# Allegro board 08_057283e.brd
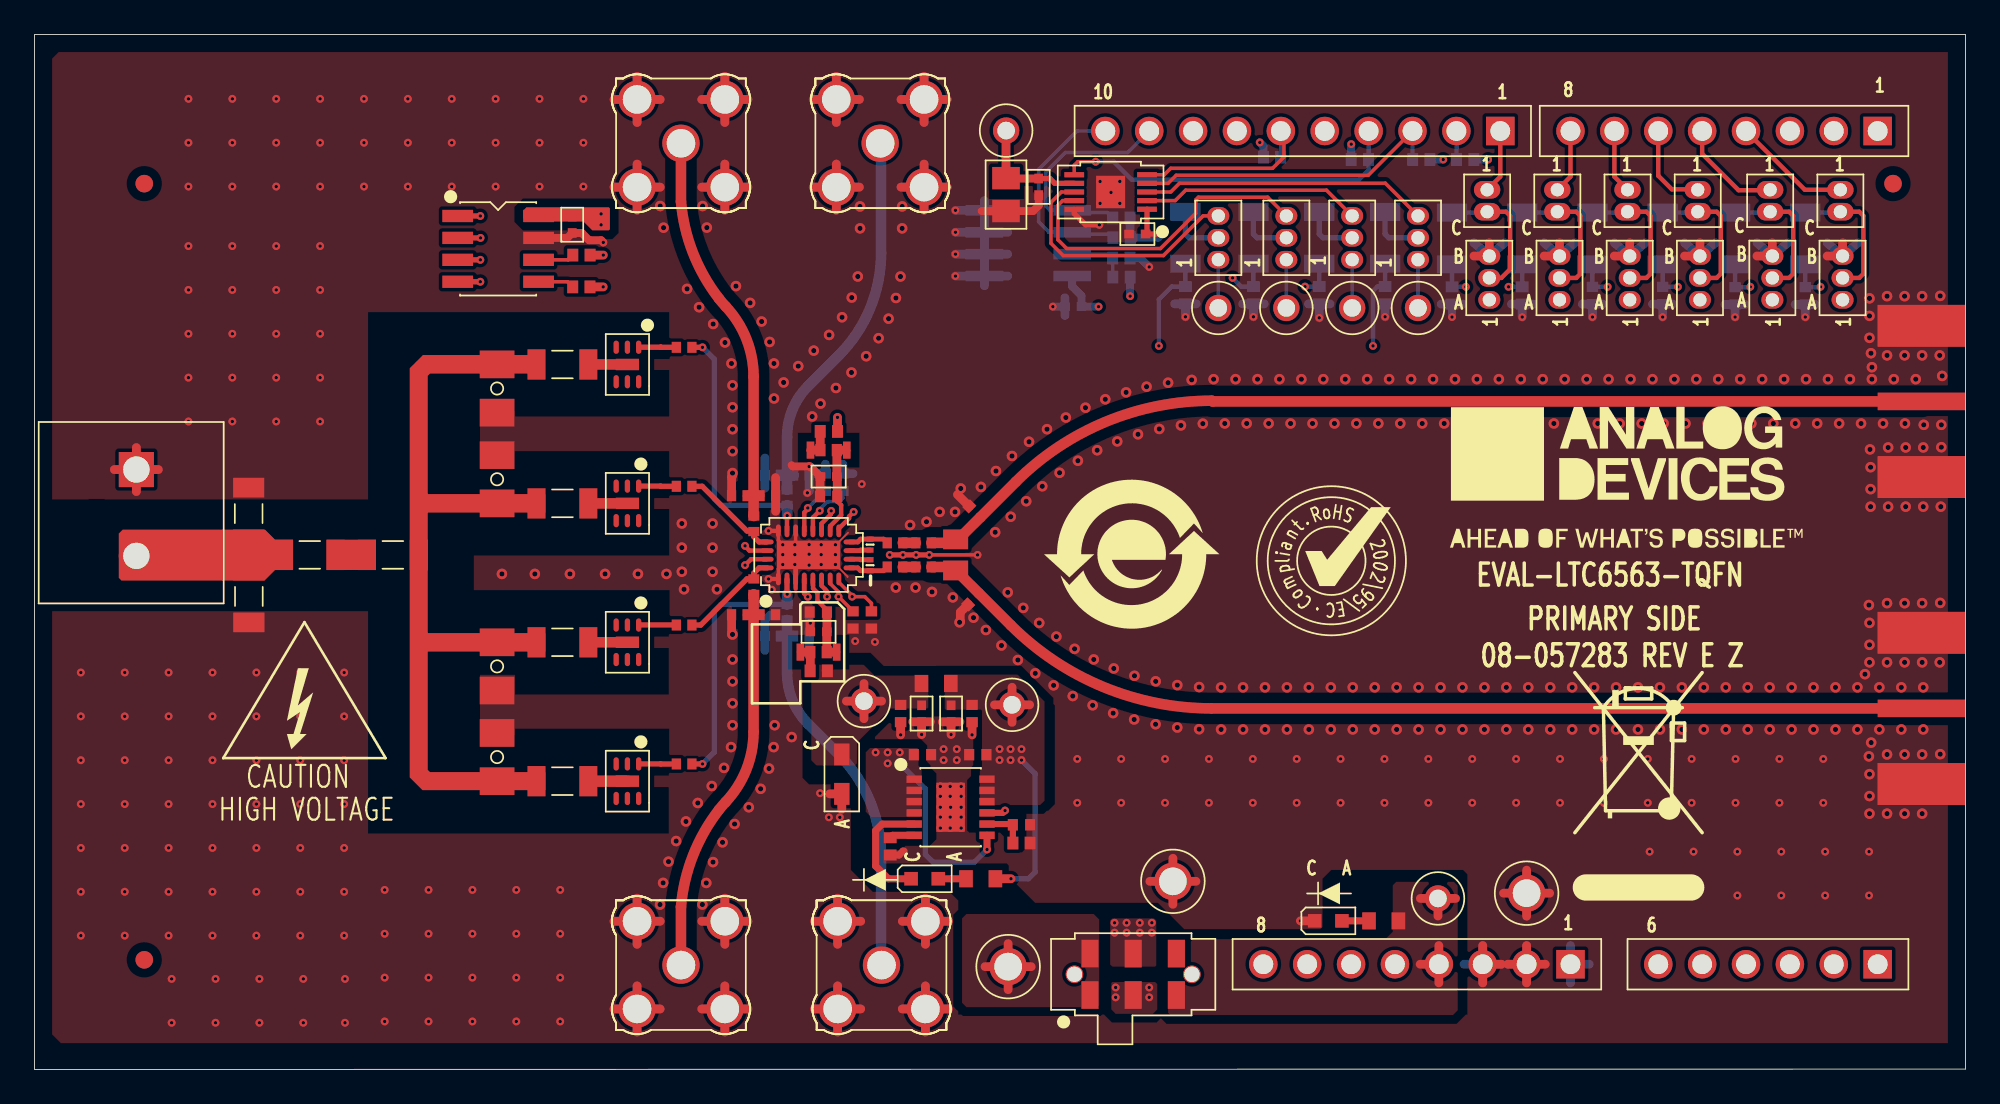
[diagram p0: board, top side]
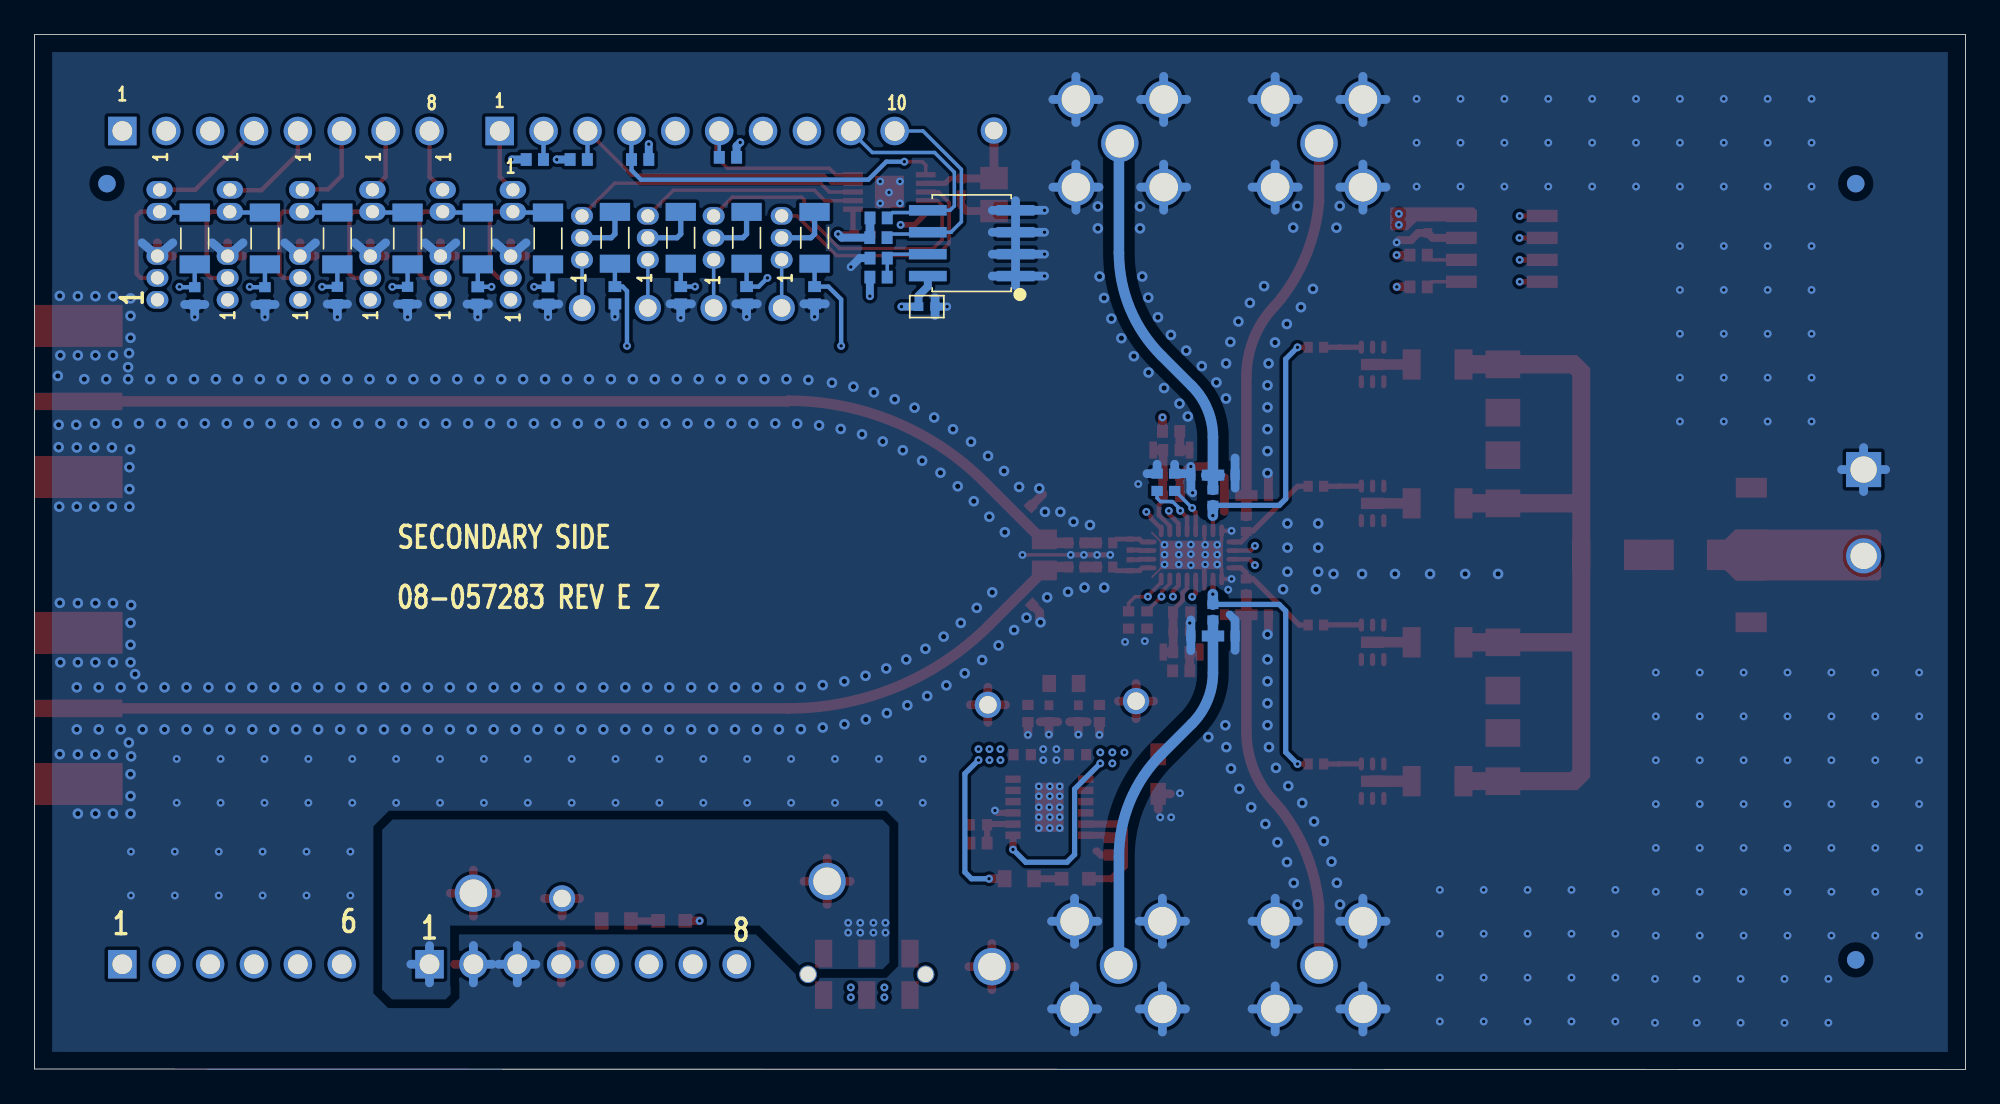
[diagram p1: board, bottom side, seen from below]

Outline 111.76 x 59.94 mm; copper layers: TOP, L2_GND, L3_VCC, L4_SIGNAL, L5_GND, BOTTOM. Coordinates in mm from the lower left corner of the outline.
Outline path: 0,59.94 0,0 111.76,0.03 111.76,59.94 0,59.94

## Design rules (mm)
constraint set DEFAULT: min track width 0.203

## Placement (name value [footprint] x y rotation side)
ADJ0  FTS-103-01-F-S  [CN1X3H159]  104.65 44.58 90 top
ADJ1  FTS-103-01-F-S  [CN1X3H159]  100.58 44.58 90 top
C1  680pF  [C0402]  45.77 34.01 270 bottom
C2  680pF  [C0402]  47.37 26.03 90 top
C3  680pF  [C0402]  46.79 34.01 270 bottom
C4  680pF  [C0402]  48.44 26.03 270 top
C5  0.1uF  [C0402H22]  60.12 44.18 180 bottom
C6  0.1uF  [C0402H22]  31.12 48.93 90 top
C7  1000pF  [C1206]  12.39 32.2 270 top
C8  1000pF  [C1206]  12.4 27.4 90 top
C9  0.1uF  [C1206H71]  26.77 39.44 90 top
C10  0.1uF  [C1206H71]  26.77 34.19 270 top
C11  0.1uF  [C1206H71]  26.77 23.35 90 top
C12  0.1uF  [C1206H71]  26.77 18.09 270 top
C13  10uF  [C0805H53]  56.23 50.67 90 top
C14  4.7uF  [C0402]  51.39 18.23 180 top
C15  0.47uF  [C0402H22]  57.12 14.17 180 top
C16  10uF  [C0402]  54.59 18.23 0 top
C17  0.1uF  [C0402H22]  45.38 25.35 0 top
C18  680pF  [C0402]  45.36 26.49 0 top
C19  1uF  [C0402H22]  51.34 20.62 90 top
C20  680pF  [C0402]  45.96 33.19 0 top
C21  10uF  [C0402]  50.13 20.62 90 top
C22  0.1uF  [C0402H22]  45.96 34.34 0 top
C25  10uF  [C0402]  54.26 20.62 90 top
C26  0.1uF  [C0402H22]  63.83 48.39 0 top
C27  0.1uF  [C0402H22]  58.12 51.12 90 top
C28  4.7pF  [C0805]  53.31 29.8 90 top
C29  1uF  [C0402H22]  53.05 20.62 90 top
CHSEL0  FTS-103-01-F-S  [CN1X3H159]  84.2 44.58 90 top
CHSEL1  FTS-103-01-F-S  [CN1X3H159]  88.27 44.58 90 top
CM  BLK  [CNKEY5001TP]  68.52 44.11 90 top
D1  501557  [DFN6_2X2_PAD1_35X0_65]  34.32 40.83 180 top
D2  501557  [DFN6_2X2_PAD1_35X0_65]  34.32 32.79 180 top
D3  501557  [DFN6_2X2_PAD1_35X0_65]  34.32 24.74 180 top
D4  501557  [DFN6_2X2_PAD1_35X0_65]  34.32 16.7 180 top
D5  SD101CWS-7-F  [SOD323]  46.72 17.11 270 top
DS1  SML-LX0603GW-TR  [LED0603-2]  74.88 8.61 0 top
DS2  SML-LX0603GW-TR  [LED0603-2]  51.52 11.05 0 top
E1  1.8K OHM AT 100MEGHZ  [L0402]  45.38 24.17 0 top
E2  1.8K OHM AT 100MEGHZ  [L0402]  45.96 35.87 180 top
GND  BLK  [CNLOOPTP]  65.89 10.9 0 top
GND1  BLK  [CNLOOPTP]  86.36 10.21 0 top
HI  BLK  [CNKEY5001TP]  80.07 44.11 90 top
IN1  SMA-J-P-H-ST-TH1  [CNSMASQ276H381]  48.95 53.64 90 top
IN2  SMA-J-P-H-ST-TH1  [CNSMASQ276H381]  37.41 53.64 90 top
IN3  SMA-J-P-H-ST-TH1  [CNSMASQ276H381]  37.41 6.05 270 top
IN4  SMA-J-P-H-ST-TH1  [CNSMASQ276H381]  49.02 6.05 270 top
MUX  FTS-103-01-F-S  [CN1X3H159]  92.33 44.58 90 top
NOREF  -  []  15.37 20.83 0 top
NOREF#2  -  []  -231.78 -199.64 0 top
NOREF#3  -  []  139.57 144.91 0 top
NOREF#4  -  []  0 59.94 0 top
NOREF#5  -  []  6.35 6.35 0 top
NOREF#6  -  []  113.03 0 0 top
NOREF#7  -  []  102.11 26.67 0 top
NOREF#8  -  []  -231.78 -199.64 0 top
NOREF#9  -  []  63.5 29.84 0 top
NOREF#10  -  []  -47.62 251.21 0 top
NOREF#11  -  []  158.11 260.48 0 top
NOREF#12  -  []  0 59.94 0 top
NOREF#13  -  []  -231.78 -199.64 0 top
NOREF#14  -  []  91.57 34.29 0 top
NOREF#15  -  []  0 59.94 270 top
NOREF#16  -  []  111.76 0 90 top
NOREF#17  -  []  0 0 0 top
NOREF#18  -  [unnamed#2]  6.35 6.35 0 top
NOREF#19  -  []  208.91 -40.39 0 top
NOREF#20  -  [unnamed#2]  6.35 51.31 0 top
NOREF#21  -  []  111.76 59.94 180 top
NOREF#22  -  []  0 0 0 top
NOREF#23  -  []  6.35 6.35 0 top
NOREF#24  -  []  75.06 29.46 0 top
NOREF#25  -  []  112.39 79.12 270 top
NOREF#26  -  [unnamed#2]  107.57 51.31 0 top
NOREF#27  -  []  43.18 3.56 270 top
NOREF#28  -  []  0 0 0 top
NOREF#29  -  []  57.66 74.42 0 top
NOREF#30  -  []  -1.27 32.26 0 top
NOREF#31  -  []  111.76 0 0 top
NOREF#32  -  [unnamed#2]  107.57 51.31 180 bottom
NOREF#33  -  [unnamed#2]  6.35 51.31 180 bottom
NOREF#34  -  [unnamed#2]  6.35 6.35 180 bottom
OFFSET  BLK  [CNKEY5001TP]  76.26 44.11 90 top
OUT  142-0701-801  [CNJOHNSON142-0701-801]  109.22 38.69 0 top
OUTBAR  142-0701-801  [CNJOHNSON142-0701-801]  109.22 20.91 0 top
P1  FTS-103-01-F-S  [CN1X3H159]  68.52 46.9 90 top
P2  FTS-103-01-F-S  [CN1X3H159]  72.45 46.9 90 top
P3  FTS-103-01-F-S  [CN1X3H159]  76.26 46.9 90 top
P4  FTS-103-01-F-S  [CN1X3H159]  80.07 46.9 90 top
P7  MC000046  [CNMULTICOMP-MC000046]  5.89 34.75 270 top
P8  SSQ-110-03-G-S  [CNSAMTECSSQ-110-XX-X-S]  84.84 54.36 180 top
P9  SSQ-108-03-G-S  [CNSAMTECSSQ-108-XX-X-S]  106.68 54.36 180 top
P10  SSQ-106-03-G-S  [CNSAMTECSSQ-106-XX-X-S]  106.68 6.1 180 top
P11  SSQ-108-03-G-S  [CNSAMTECSSQ-108-XX-X-S]  88.9 6.1 180 top
P13  FTS-102-01-F-S  [CNSAMTECFTS-102-01-F-S]  88.14 50.95 270 top
P14  FTS-102-01-F-S  [CNSAMTECFTS-102-01-F-S]  96.27 50.95 270 top
P15  FTS-102-01-F-S  [CNSAMTECFTS-102-01-F-S]  92.2 50.95 270 top
P19  FTS-102-01-F-S  [CNSAMTECFTS-102-01-F-S]  84.07 50.95 270 top
P20  FTS-102-01-F-S  [CNSAMTECFTS-102-01-F-S]  104.52 50.95 270 top
P21  FTS-102-01-F-S  [CNSAMTECFTS-102-01-F-S]  100.46 50.95 270 top
R1  100  [R0402]  42.72 34.43 0 bottom
R2  100  [R0402]  40.79 33.23 0 top
R3  100  [R0402]  42.44 26.34 180 top
R4  100  [R0402]  44.38 25.11 180 bottom
R5  100  [R0402]  44.38 34.43 180 bottom
R6  100  [R0402]  42.44 33.23 180 top
R7  100  [R0402]  40.79 26.34 0 top
R8  100  [R0402]  42.72 25.11 0 bottom
R9  33  [R1206]  70.55 48.17 270 bottom
R10  33  [R1206]  66.61 48.17 270 bottom
R11  33  [R1206]  74.36 48.17 270 bottom
R12  33  [R1206]  78.17 48.17 270 bottom
R13  10K  [R0402]  70.55 44.84 90 bottom
R14  10K  [R0402]  66.61 44.84 90 bottom
R15  10K  [R0402]  74.36 44.84 90 bottom
R16  10K  [R0402]  78.17 44.84 90 bottom
R17  33  [R1206]  94.23 48.13 270 bottom
R18  33  [R1206]  90.17 48.13 270 bottom
R19  33  [R1206]  102.49 48.13 270 bottom
R20  33  [R1206]  98.42 48.13 270 bottom
R21  0.1uF  [C0402H22]  94.23 44.83 90 bottom
R22  0.1uF  [C0402H22]  90.17 44.83 90 bottom
R23  0.1uF  [C0402H22]  102.49 44.81 90 bottom
R24  0.1uF  [C0402H22]  98.42 44.81 90 bottom
R25  33  [R1206]  86.11 48.13 270 bottom
R26  33  [R1206]  82.04 48.13 270 bottom
R27  10K  [R0402]  86.11 44.83 270 bottom
R28  10K  [R0402]  82.04 44.83 270 bottom
R29  10K  [R1206]  15.93 29.8 0 top
R30  10K  [R1206]  20.74 29.8 0 top
R31  49.9  [R1206]  30.55 40.83 0 top
R32  49.9  [R1206]  30.55 32.79 0 top
R33  49.9  [R1206]  30.55 24.74 0 top
R34  49.9  [R1206]  30.55 16.7 0 top
R39  0  [R0402]  37.6 41.83 0 top
R40  0  [R0402]  37.6 33.78 0 top
R41  0  [R0402]  37.6 25.74 0 top
R42  0  [R0402]  37.6 17.7 0 top
R43  10K  [R0402]  31.65 47.17 0 top
R44  10K  [R0402]  31.65 45.33 0 top
R45  33.2K  [R0402]  57.12 13.11 180 top
R46  0  [R0402]  45.39 23.09 180 top
R47  0  [R0201]  48.36 30.4 270 top
R48  0  [R0201]  48.36 29.21 270 top
R49  0  [R0603]  52.18 22.36 0 top
R50  0  [R0402]  45.97 36.96 0 top
R51  0  [R0402]  49.8 30.5 0 top
R52  0  [R0402]  49.8 29.11 0 top
R53  0  [R0402]  51.46 30.5 0 top
R54  0  [R0402]  51.46 29.11 0 top
R55  49.9  [R0402]  54.42 32.3 135 top
R56  49.9  [R0402]  54.35 27.25 45 top
R57  10K  [R0402]  62.92 48.18 0 bottom
R58  10K  [R0402]  62.91 45.89 0 bottom
R59  0  [R0402]  62.9 46.99 180 bottom
R60  10K  [R0402]  62.91 49.32 0 bottom
R61  150  [R0603]  78.09 8.61 0 top
R62  0  [R0402]  49.53 12.92 90 top
R63  110  [R0603]  54.76 11.05 0 top
R64  2K  [R0402]  43.55 33.12 270 bottom
R65  2K  [R0402]  41.63 31.61 270 top
R66  2K  [R0402]  41.63 27.97 90 top
R67  2K  [R0402]  43.55 26.48 90 bottom
R68  10K  [R0402]  82.8 52.7 0 bottom
R69  10K  [R0402]  80.26 52.7 0 bottom
R70  10K  [R0402]  76.71 52.7 180 bottom
R71  10K  [R0402]  71.63 52.83 180 bottom
REF  BLK  [CNKEY5001TP]  56.24 54.38 0 top
S1  JS202011JAQN  [SWSML354W142H142]  63.59 5.51 0 top
SHDN  FTS-103-01-F-S  [CN1X3H159]  96.39 44.58 90 top
TILT  BLK  [CNKEY5001TP]  72.45 44.11 90 top
TP4  BLK  [CNKEY5001TP]  81.23 9.91 0 top
U1  ADT7311WTRZ  [SO8-2]  26.83 47.53 270 top
U2  LTC2634IMSE-LMI10#PBF  [MSOP10_PAD1_88X1_68]  62.28 50.82 90 top
U3  LT3045HMSE#PBF  [MSOP12_PAD2_845X1_651]  53.02 15.19 270 top
U4  LTC6563  [QFN24_5X3_PAD3_65X1_65]  44.8 29.8 0 top
U5  24AA256-I/SN  [SO8]  57.52 47.86 90 bottom
VCCI  BLK  [CNKEY5001TP]  48.01 21.34 0 top
VCCO  BLK  [CNKEY5001TP]  56.58 21.12 0 top
VIN  RED  [CNLOOPTP]  56.35 5.96 0 top

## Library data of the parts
ADJ0 ADJ1 CHSEL0 CHSEL1 MUX P1-P4 SHDN = CN3P: Tolerance: N/A; User Part Number: UPN; alternate symbols: (); part number: CN3P_TH-FTS-103-01-F-S,E021702,CN1X3H159; tolerance: N/A
C1-C4 C18 C20 = CAP: User Part Number: UPN; Tolerance: 10; alternate symbols: (C0402L); part number: CAP_SM-680PF,50V,10,E033952,C0402; tolerance: 10
C5 C6 C17 C22 C26 C27 = CAP: Tolerance: 10; User Part Number: UPN; alternate symbols: (); part number: CAP_SM-0.1UF,50V,10,E018452,C0402H22; tolerance: 10
C7 C8 = CAP: User Part Number: UPN; Tolerance: 20; alternate symbols: (C1206L); part number: CAP_SM-1000PF,2000V,20,E033416,C1206; tolerance: 20
C9-C12 = CAP: Tolerance: 10; User Part Number: UPN; alternate symbols: (); part number: CAP_SM-0.1UF,450V,10,E019762,C1206H71; tolerance: 10
C13 = CAP: Tolerance: 10; User Part Number: UPN; alternate symbols: (); part number: CAP_SM-10UF,16V,10,E006166,C0805H53; tolerance: 10
C14 = CAP: User Part Number: UPN; Tolerance: 10; alternate symbols: (C0402L); part number: CAP_SM-4.7UF,10V,10,E028571,C0402; tolerance: 10
C15 = CAP: User Part Number: UPN; Tolerance: 10; alternate symbols: C0402; part number: CAP_SM-0.47UF,10V,10,E030959,C0402H22; tolerance: 10
C16 C21 C25 = CAP: User Part Number: UPN; Tolerance: 20; alternate symbols: (C0402L); part number: CAP_SM-10UF,10V,20,E020928,C0402; tolerance: 20
C19 C29 = CAP: Tolerance: 20; User Part Number: UPN; alternate symbols: (); part number: CAP_SM-1UF,25V,20,E028570,C0402H22; tolerance: 20
C28 = CAP: User Part Number: UPN; Tolerance: 0.1pF; alternate symbols: (); part number: CAP_SM-4.7PF,250V,0.1PF,E024708,C0805; tolerance: 0.1pF
CM HI OFFSET REF TILT TP4 VCCI VCCO = CNTP1P: Tolerance: N/A; User Part Number: UPN; alternate symbols: (); part number: CNTP1P_TH-BLK,E005347,CNKEY5001TP; tolerance: N/A
D1-D4 = DIOPHOTO6P_V3: Tolerance: N/A; User Part Number: UPN; alternate symbols: (); part number: DIOPHOTO6P_V3_SM-501557,200V,N/A,E034727,DFN6_2X2_PAD1_35X0_65; tolerance: N/A
D5 = DIOSCHOTTKY: Tolerance: N/A; User Part Number: UPN; alternate symbols: (); part number: DIOSCHOTTKY_SM-SD101CWS-7-F,40V,N/A,E032391,SOD323; tolerance: N/A
DS1 DS2 = DIOLED: Tolerance: N/A; User Part Number: UPN; alternate symbols: (); part number: DIOLED_SM-SML-LX0603GW-TR,N/A,N/A,E018702,LED0603-2; tolerance: N/A
E1 E2 = FERRITE: User Part Number: UPN; Tolerance: 25; alternate symbols: (L0402L); part number: FERRITE_SM-1.8K OHM AT 100MEGHZ,25,E025769,L0402; tolerance: 25
GND GND1 = CNTP1P: User Part Number: UPN; Tolerance: N/A; alternate symbols: (); part number: CNTP1P_TH-BLK,E000948,CNLOOPTP; tolerance: N/A
IN1-IN4 = CNBNC5P: User Part Number: UPN; Tolerance: N/A; alternate symbols: (); part number: CNBNC5P_TH-SMA-J-P-H-ST-TH1,E035738,CNSMASQ276H381; tolerance: N/A
OUT OUTBAR = CNBNC5P: User Part Number: UPN; Tolerance: N/A; alternate symbols: (); part number: CNBNC5P_SM-142-0701-801,E000914,CNJOHNSON142-0701-801; tolerance: N/A
P7 = CN2P: User Part Number: UPN; Tolerance: N/A; alternate symbols: (); part number: CN2P_TH-MC000046,E024272,CNMULTICOMP-MC000046; tolerance: N/A
P8 = CN10P: User Part Number: UPN; Tolerance: N/A; alternate symbols: (); part number: CN10P_TH-SSQ-110-03-G-S,E020479,CNSAMTECSSQ-110-XX-X-S; tolerance: N/A
P9 P11 = CN8P_A: User Part Number: UPN; Tolerance: N/A; alternate symbols: (); part number: CN8P_A_TH-SSQ-108-03-G-S,E020478,CNSAMTECSSQ-108-XX-X-S; tolerance: N/A
P10 = CN6P: User Part Number: UPN; Tolerance: N/A; alternate symbols: (); part number: CN6P_TH-SSQ-106-03-G-S,E020477,CNSAMTECSSQ-106-XX-X-S; tolerance: N/A
P13-P15 P19-P21 = CN2P: Tolerance: N/A; User Part Number: UPN; alternate symbols: (); part number: CN2P_TH-FTS-102-01-F-S,E021754,CNSAMTECFTS-102-01-F-S; tolerance: N/A
R1-R8 = RES: User Part Number: UPN; Tolerance: 1; alternate symbols: (R0402L); part number: RES_SM-100,E016329,1/10W,1,R0402; tolerance: 1
R9-R12 R17-R20 R25 R26 = RES: User Part Number: UPN; Tolerance: 2; alternate symbols: (R1206L); part number: RES_SM-33,E004120,1/4W,2,R1206; tolerance: 2
R13-R16 R27 R28 R43 R44 R57 R58 R60 R68-R71 = RES: User Part Number: UPN; Tolerance: 1; alternate symbols: (R0402L,R0402L_ALT); part number: RES_SM-10K,E003751,1/10W,1,R0402; tolerance: 1
R21-R24 = CAP: User Part Number: UPN; Tolerance: 10; alternate symbols: C0402; part number: CAP_SM-0.1UF,50V,10,E018452,C0402H22; tolerance: 10
R29 R30 = RES: User Part Number: UPN; Tolerance: 1; alternate symbols: (R1206L); part number: RES_SM-10K,E003285,1/4W,1,R1206; tolerance: 1
R31-R34 = RES: User Part Number: UPN; Tolerance: 1; alternate symbols: (R1206L); part number: RES_SM-49.9,E003114,1/4W,1,R1206; tolerance: 1
R39-R42 R46 R50-R54 R59 R62 = RES: User Part Number: UPN; Tolerance: JUMPER; alternate symbols: (R0402L); part number: RES_SM-0,E025226,1/16W,JUMPER,R0402; tolerance: JUMPER
R45 = RES: User Part Number: UPN; Tolerance: 1; alternate symbols: (R0402L); part number: RES_SM-33.2K,E020578,1/16W,1,R0402; tolerance: 1
R47 R48 = RES: Tolerance: 5; User Part Number: UPN; alternate symbols: (R0201L); part number: RES_SM-0,E032382,1/20W,5,R0201; tolerance: 5
R49 = RES: User Part Number: UPN; Tolerance: JUMPER; alternate symbols: (R0603L); part number: RES_SM-0,E006826,1/10W,JUMPER,R0603; tolerance: JUMPER
R55 R56 = RES: User Part Number: UPN; Tolerance: 1; alternate symbols: (R0402L); part number: RES_SM-49.9,E014717,1/8W,1,R0402; tolerance: 1
R61 = RES: User Part Number: UPN; Tolerance: 0.1; alternate symbols: (R0603L); part number: RES_SM-150,E013609,1/10W,0.1,R0603; tolerance: 0.1
R63 = RES: User Part Number: UPN; Tolerance: 1; alternate symbols: (R0603L); part number: RES_SM-110,E033970,1/10W,1,R0603; tolerance: 1
R64-R67 = RES: User Part Number: UPN; Tolerance: 5; alternate symbols: (R0402L); part number: RES_SM-2K,E012359,1/16W,5,R0402; tolerance: 5
S1 = SWDPDT_V7: Tolerance: N/A; User Part Number: UPN; alternate symbols: (); part number: SWDPDT_V7_SM-JS202011JAQN,E033200,SWSML354W142H142; tolerance: N/A
U1 = ADT7311: Tolerance: N/A; User Part Number: UPN; alternate symbols: (); part number: ADT7311_SM-ADT7311WTRZ,E035551,SO8-2; tolerance: N/A
U2 = ADLTC2634: User Part Number: UPN; Tolerance: N/A; alternate symbols: (); part number: ADLTC2634_SM-LTC2634IMSE-LMI10#PBF,E040099,MSOP10_PAD1_88X1_68; tolerance: N/A
U3 = LINLT3045: Tolerance: N/A; User Part Number: UPN; alternate symbols: (); part number: LINLT3045_SM-LT3045HMSE#PBF,E034148,MSOP12_PAD2_845X1_651; tolerance: N/A
U4 = ADLTC6563_V2: User Part Number: UPN; Tolerance: N/A; alternate symbols: (); part number: ADLTC6563_V2_SM-LTC6563,E036034,QFN24_5X3_PAD3_65X1_65; tolerance: N/A
U5 = IC24FC256: Tolerance: N/A; User Part Number: UPN; alternate symbols: (); part number: IC24FC256_SM-24AA256-I/SN,E008084,SO8; tolerance: N/A
VIN = CNTP1P: User Part Number: UPN; Tolerance: N/A; alternate symbols: (); part number: CNTP1P_TH-RED,E000947,CNLOOPTP; tolerance: N/A

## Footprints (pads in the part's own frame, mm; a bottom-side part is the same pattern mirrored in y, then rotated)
C0402
  rect 0.584x0.66 smd: 1(-0.5,0) 2(0.5,0)
C0402H22
  rect 0.559x0.508 smd: 1(-0.479,0) 2(0.479,0)
C0805
  rect 1.143x1.448 smd: 1(-0.9,0) 2(0.9,0)
C0805H53
  rect 1.295x1.6 smd: 1(-0.953,0) 2(0.953,0)
C1206
  rect 1.143x1.803 smd: 1(-1.5,0) 2(1.5,0)
C1206H71
  rect 1.6x2.007 smd: 1(-1.397,0) 2(1.397,0)
CN1X3H159
  oval 1.016x1.27 hole 0.762: 1(0,0) 2(1.27,0) 3(2.54,0)
CNJOHNSON142-0701-801
  rect 5.08x1.016 smd: 1(0,0)
  rect 5.08x2.413 smd: 2(0,4.381) 3(0,4.381) 4(0,-4.381) 5(0,-4.381)
CNKEY5001TP
  round 1.524 hole 1.016: 1(0,0)
CNLOOPTP
  round 2.159 hole 1.6: 1(0,0)
CNMULTICOMP-MC000046
  rect 2.032x2.032 hole 1.524: 1(0,0)
  round 2.032 hole 1.524: 2(5,0)
CNSAMTECFTS-102-01-F-S
  oval 1.016x1.524 hole 0.762: 1(0,0) 2(1.27,0)
CNSAMTECSSQ-106-XX-X-S
  rect 1.651x1.651 hole 1.143: 1(0,0)
  round 1.651 hole 1.143: 2(2.54,0) 3(5.08,0) 4(7.62,0) 5(10.16,0) 6(12.7,0)
CNSAMTECSSQ-108-XX-X-S
  rect 1.651x1.651 hole 1.143: 1(0,0)
  round 1.651 hole 1.143: 2(2.54,0) 3(5.08,0) 4(7.62,0) 5(10.16,0) 6(12.7,0) 7(15.24,0) 8(17.78,0)
CNSAMTECSSQ-110-XX-X-S
  rect 1.651x1.651 hole 1.143: 1(0,0)
  round 1.651 hole 1.143: 2(2.54,0) 3(5.08,0) 4(7.62,0) 5(10.16,0) 6(12.7,0) 7(15.24,0) 8(17.78,0) 9(20.32,0) 10(22.86,0)
CNSMASQ276H381
  round 2.159 hole 1.651: 1(0,0) 2(-2.54,2.54) 3(2.54,2.54) 4(-2.54,-2.54) 5(2.54,-2.54)
DFN6_2X2_PAD1_35X0_65
  oval 0.305x0.762 smd: 1(-0.65,-1) 2(0,-1) 3(0.65,-1) 4(0.65,1) 5(0,1) 6(-0.65,1)
  rect 1.346x0.66 smd: PAD(0,0)
L0402
  rect 0.584x0.711 smd: 1(-0.475,0) 2(0.475,0)
LED0603-2
  rect 0.787x0.787 smd: A(0.787,0) C(-0.787,0)
MSOP10_PAD1_88X1_68
  rect 0.305x1.143 smd: 1(-1,-2.106) 2(-0.5,-2.106) 3(0,-2.106) 4(0.5,-2.106) 5(1,-2.106) 6(1,2.106) 7(0.5,2.106) 8(0,2.106) 9(-0.5,2.106) 10(-1,2.106)
  rect 1.88x1.676 smd: PAD(0,0)
MSOP12_PAD2_845X1_651
  rect 0.432x0.889 smd: 1(-1.625,-2.107) 2(-0.975,-2.107) 3(-0.325,-2.107) 4(0.325,-2.107) 5(0.975,-2.107) 6(1.625,-2.107) 7(1.625,2.107) 8(0.975,2.107) 9(0.325,2.107) 10(-0.325,2.107) 11(-0.975,2.107) 12(-1.625,2.107)
  rect 2.845x1.651 smd: PAD(0,0)
QFN24_5X3_PAD3_65X1_65
  oval 0.279x0.737 smd: 1(-1.75,-1.393) 2(-1.25,-1.393) 3(-0.75,-1.393) 4(-0.25,-1.393) 5(0.25,-1.393) 6(0.75,-1.393) 7(1.25,-1.393) 8(1.75,-1.393) 13(1.75,1.393) 14(1.25,1.393) 15(0.75,1.393) 16(0.25,1.393) 17(-0.25,1.393) 18(-0.75,1.393) 19(-1.25,1.393) 20(-1.75,1.393)
  oval 0.737x0.279 smd: 9(2.393,-0.75) 10(2.393,-0.25) 11(2.393,0.25) 12(2.393,0.75) 21(-2.393,0.75) 22(-2.393,0.25) 23(-2.393,-0.25) 24(-2.393,-0.75)
  rect 3.658x1.651 smd: PAD(0,0)
R0201
  rect 0.305x0.406 smd: 1(-0.318,0) 2(0.318,0)
R0402
  rect 0.635x0.737 smd: 1(-0.5,0) 2(0.5,0)
R0603
  rect 0.787x0.991 smd: 1(-0.85,0) 2(0.85,0)
R1206
  rect 1.041x1.753 smd: 1(-1.5,0) 2(1.5,0)
SO8
  rect 0.61x2.184 smd: 1(-1.905,-2.54) 2(-0.635,-2.54) 3(0.635,-2.54) 4(1.905,-2.54) 5(1.905,2.54) 6(0.635,2.54) 7(-0.635,2.54) 8(-1.905,2.54)
SO8-2
  rect 0.711x1.778 smd: 1(-1.905,-2.341) 2(-0.635,-2.341) 3(0.635,-2.341) 4(1.905,-2.341) 5(1.905,2.341) 6(0.635,2.341) 7(-0.635,2.341) 8(-1.905,2.341)
SOD323
  rect 1.27x0.889 smd: A(1.143,0) C(-1.143,0)
SWSML354W142H142
  round 1.016 hole 0.889 unplated: (-3.4,0) (3.4,0)
  rect 0.991x1.6 smd: 1(-2.5,-1.2) 2(0,-1.2) 3(2.5,-1.2) 5(-2.5,1.2) 6(0,1.2) 7(2.5,1.2)
unnamed#2
  round 1.016 smd: (0,0)

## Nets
+5V_DC2026C_VOUT: P11.4 R61.2(N2) S1.3 TP4.1(N1)
DGND: P8.7
GND: ADJ0.3(N3) ADJ1.3(N3) C1.1 C2.1 C3.1 C4.2(N2) C5.2(N2) C6.1 C7.1 C8.1 C9.1 C10.1 C11.1 C12.1 C13.1 C14.1 C15.1 C16.1 C17.1 C18.1 C19.1 C20.1 C21.1 C22.1 C25.1 C26.1 C27.1 C29.1 CHSEL0.3(N3) CHSEL1.3(N3) D5.A(P) DS1.C GND.1(N1) GND1.1(N1) IN1.2 IN1.3 IN1.4 IN1.5(SH4) IN2.2 IN2.3 IN2.4 IN2.5(SH4) IN3.2 IN3.3 IN3.4 IN3.5(SH4) IN4.2 IN4.3 IN4.4 IN4.5(SH4) MUX.3(N3) OUT.2 OUT.3 OUT.4 OUT.5(SH4) OUTBAR.2 OUTBAR.3 OUTBAR.4 OUTBAR.5(SH4) P7.1 P11.2 P11.3 R1.1 R2.1 R3.1 R4.1 R5.1 R6.1 R7.1 R8.1 R13.1 R14.1 R15.1 R16.1 R21.1 R22.1 R23.1 R24.1 R27.2(N2) R28.2(N2) R45.1 R55.2(N2) R56.1 R59.1 R62.1 SHDN.3(N3) U1.7 U2.10 U2.PAD U3.9 U3.PAD U4.1 U4.3 U4.18 U4.20 U4.PAD U5.1 U5.2 U5.3 U5.4
VCCI: C19.2(N2) C21.2(N2) D5.C R46.1 R49.1 VCCI.1(N1)
VCCO: ADJ0.1 ADJ1.1 C5.1 C6.2(N2) C16.2(N2) C25.2(N2) C26.2(N2) C29.2(N2) CHSEL0.1 CHSEL1.1 MUX.1 R43.2(N2) R44.2(N2) R49.2(N2) R50.2(N2) R57.2(N2) R58.2(N2) R60.2(N2) R63.2(N2) R68.2(N2) R69.2(N2) R70.2(N2) R71.2(N2) SHDN.1 U1.8(VDD) U2.1 U3.10 U3.11 U3.12 U5.8 VCCO.1(N1)
DAC_CM: P1.3(N3) U2.8
DAC_CS: P8.3 R69.1 U2.4
DAC_HI: P4.3(N3) U2.3
DAC_OFFSET: P3.3(N3) U2.2
DAC_TILT: P2.3(N3) U2.9(VOUTD)
DC2026C_ADJ0: P9.4 P20.1
DC2026C_ADJ1: P9.5 P21.1
DC2026C_CHSEL0: P8.1 P19.1
DC2026C_CHSEL1: P9.8(N8) P13.1
DC2026C_O_MUX: P9.7 P15.1
DC2026C_SHDN: P9.6 P14.1
DC2026C_VIN: P11.1 S1.6
EEPROM_SCL: P8.10 R57.1 U5.6
EEPROM_SDA: P8.9(N9) R60.1 U5.5
IN1: R39.2(N2) R64.2(N2) U4.19
IN2: R40.2(N2) R65.2(N2) U4.21
IN3: R41.2(N2) R66.2(N2) U4.24
IN4: R42.2(N2) R67.2(N2) U4.2
LTC6563_ADJ0: R19.2(N2) R23.2(N2) U4.22
LTC6563_ADJ1: R20.2(N2) R24.2(N2) U4.23
LTC6563_CHSEL0: R26.2(N2) R28.1 U4.15
LTC6563_CHSEL1: R25.2(N2) R27.1 U4.13
LTC6563_CM: C2.2(N2) R10.2(N2) R14.2(N2) U4.7
LTC6563_HI: C4.1 R12.2(N2) R16.2(N2) U4.8
LTC6563_O_MUX: R18.2(N2) R22.2(N2) U4.6
LTC6563_OFFSET: C3.2(N2) R11.2(N2) R15.2(N2) U4.16
LTC6563_SHDN: R17.2(N2) R21.2(N2) U4.4
LTC6563_TILT: C1.2(N2) R9.2(N2) R13.2(N2) U4.17
SPI_MISO: P8.5 U1.2
SPI_MOSI: P8.4 R70.1 U1.3 U2.6
SPI_SCK: P8.6 R71.1 U1.1 U2.5
TEMP_CS: P8.2 R68.1 U1.4
UNNAMED_4_ADLTC2634_I71_REF: C13.2(N2) C27.2(N2) REF.1(N1) U2.7
UNNAMED_4_ADT7311_I26_CT: R43.1 U1.6
UNNAMED_4_ADT7311_I26_INT: R44.1 U1.5
UNNAMED_4_CAP_I11_N2: C15.2(N2) R45.2(N2) U3.8(SET)
UNNAMED_4_CAP_I12_N2: C14.2(N2) S1.2 U3.1 U3.2 U3.3 U3.4 U3.7
UNNAMED_4_CNTP1P_I76_N1: S1.1 S1.5 VIN.1(N1)
UNNAMED_4_DIOLED_I57_N: DS2.C U3.5
UNNAMED_4_DIOLED_I57_P: DS2.A(P) R63.1
UNNAMED_4_DIOLED_I60_P: DS1.A(P) R61.1
UNNAMED_4_IC24FC256_I37_WP: R58.1 R59.2(N2) U5.7(WP)
UNNAMED_4_LINLT3045_I8_ILIM: R62.2(N2) U3.6
UNNAMED_6_ADLTC6563V2_I190_TERM: R47.2(N2) U4.11
UNNAMED_6_ADLTC6563V2_I190_TERMN: R48.1 U4.10
UNNAMED_6_CAP_I2_N2: C17.2(N2) C18.2(N2) E1.2(N2) U4.5
UNNAMED_6_CAP_I19_N1: C28.1 OUTBAR.1 R54.2(N2) R56.2(N2)
UNNAMED_6_CAP_I19_N2: C28.2(N2) OUT.1 R53.2(N2) R55.1
UNNAMED_6_CAP_I24_N2: C20.2(N2) C22.2(N2) E2.1 U4.14(VCCO)
UNNAMED_6_CAP_I75_N2: C7.2(N2) C8.2(N2) P7.2(N2) R29.1
UNNAMED_6_CAP_I107_N2: C9.2(N2) C10.2(N2) C11.2(N2) C12.2(N2) R30.2(N2) R31.1 R32.1 R33.1 R34.1
UNNAMED_6_CN2P_I184_N2: CHSEL1.2 P13.2(N2) R25.1
UNNAMED_6_CN2P_I185_N2: P14.2(N2) R17.1 SHDN.2
UNNAMED_6_CN2P_I186_N2: MUX.2 P15.2(N2) R18.1
UNNAMED_6_CN2P_I187_N2: ADJ1.2 P21.2(N2) R20.1
UNNAMED_6_CN2P_I188_N2: ADJ0.2 P20.2(N2) R19.1
UNNAMED_6_CN2P_I189_N2: CHSEL0.2 P19.2(N2) R26.1
UNNAMED_6_CN3P_I173_N1: P2.1 TILT.1(N1)
UNNAMED_6_CN3P_I173_N2: P2.2 R9.1
UNNAMED_6_CN3P_I175_N1: CM.1(N1) P1.1
UNNAMED_6_CN3P_I175_N2: P1.2 R10.1
UNNAMED_6_CN3P_I176_N1: OFFSET.1(N1) P3.1
UNNAMED_6_CN3P_I176_N2: P3.2 R11.1
UNNAMED_6_CN3P_I177_N1: HI.1(N1) P4.1
UNNAMED_6_CN3P_I177_N2: P4.2 R12.1
UNNAMED_6_DIOPHOTO6PV3_I91_A: D4.PAD R34.2(N2)
UNNAMED_6_DIOPHOTO6PV3_I91_C: D4.1 R42.1
UNNAMED_6_DIOPHOTO6PV3_I92_A: D3.PAD R33.2(N2)
UNNAMED_6_DIOPHOTO6PV3_I92_C: D3.1 R41.1
UNNAMED_6_DIOPHOTO6PV3_I99_A: D2.PAD R32.2(N2)
UNNAMED_6_DIOPHOTO6PV3_I99_C: D2.1 R40.1
UNNAMED_6_DIOPHOTO6PV3_I100_A: D1.PAD R31.2(N2)
UNNAMED_6_DIOPHOTO6PV3_I100_C: D1.1 R39.1
UNNAMED_6_FERRITE_I43_N2: E2.2(N2) R50.1
UNNAMED_6_FERRITE_I44_N1: E1.1 R46.2(N2)
UNNAMED_6_RES_I13_N2: R48.2(N2) R52.1 U4.9
UNNAMED_6_RES_I14_N1: R47.1 R51.1 U4.12
UNNAMED_6_RES_I15_N2: R52.2(N2) R54.1
UNNAMED_6_RES_I20_N2: R51.2(N2) R53.1
UNNAMED_6_RES_I48_N2: IN4.1 R4.2(N2) R8.2(N2) R67.1
UNNAMED_6_RES_I58_N2: IN3.1 R3.2(N2) R7.2(N2) R66.1
UNNAMED_6_RES_I64_N2: IN2.1 R2.2(N2) R6.2(N2) R65.1
UNNAMED_6_RES_I69_N2: IN1.1 R1.2(N2) R5.2(N2) R64.1
UNNAMED_6_RES_I77_N2: R29.2(N2) R30.1

Pads without a net: D1 2 3 4 5 6; D2 2 3 4 5 6; D3 2 3 4 5 6; D4 2 3 4 5 6; P8 8; P9 1 2 3; P10 1 2 3 4 5 6; P11 5 6 7 8; S1 7

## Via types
v1: diameter 0.457, hole 0.203, TOP to BOTTOM, 323 vias
v2: diameter 0.61, hole 0.305, TOP to BOTTOM, 321 vias

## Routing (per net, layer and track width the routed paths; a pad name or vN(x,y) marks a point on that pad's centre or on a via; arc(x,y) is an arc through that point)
+5V_DC2026C_VOUT: length 6.3
  TOP w0.508: P11.4 81.28,7.18 ; P11.4 80.2,6.1 ; P11.4 81.28,5.02 ; 80.21,9.91 TP4.1 ; TP4.1 81.23,8.89 ; TP4.1 82.25,9.91
GND: length 797.3
  TOP w0.102: 46.33,30.39 v1(46.36,30.39) 46.39,30.39 47.09,31.09 ; v1(46.36,29.25) 46.36,29.25 47.05,28.55 47.05,28.52
  TOP w0.203: v1(44.01,30.39) 44.05,30.44 U4.18 ; U4.20 43.05,30.65 v1(43.31,30.39) ; v1(43.31,29.25) 43.05,28.99 U4.1 ; v1(51.79,29.8) v1(54.58,29.8)
  TOP w0.254: U4.20 v1(42.48,31.2) ; U4.1 v1(42.48,28.41) ; 44.05,27.86 U4.3
  TOP w0.279: U4.3 44.05,29.2 v1(44.01,29.25)
  TOP w0.305: v1(61.63,48.92) 60.83,48.92 60.18,49.58 U2.10 ; v1(51.79,29.8) v1(51.02,29.8) v1(50.26,29.8) v1(49.5,29.8)
  TOP w0.356: U3.9 56.04,14.86 v1(56.17,15)
  TOP w0.406: R62.1 50.04,12.42 50.27,12.65 50.33,12.65
  TOP w0.457: U1.7 30.83,48.16 C6.1 31.67,48.45 32.09,48.03 32.79,48.03 v1(32.92,47.9) ; 43.82,35 43.89,34.92 v1(44.83,34.92) 44.9,34.92 C22.1 ; 54.81,49.72 C13.1 57.8,49.72 58.12,50.04 C27.1
  TOP w0.508: 92.33,47.88 92.33,47.12 91.44,47.12 ; 34.87,54.85 IN2.3 ; IN2.3 36.21,56.18 ; IN2.3 34.87,57.52 ; IN2.3 33.54,56.18 ; IN3.2 39.95,9.92 ; IN3.2 39.95,7.25 ; IN3.2 41.29,8.59 ; IN3.2 38.62,8.59 ; 103.76,47.12 104.65,47.12 104.65,47.88 ; 39.95,49.77 IN2.4 ; IN2.4 39.95,52.44 ; IN2.4 41.29,51.1 ; IN2.4 38.62,51.1 ; C22.1 45.46,34.32 C20.1 ; IN3.4 34.87,9.92 ; IN3.4 34.87,7.25 ; IN3.4 33.54,8.59 ; IN3.4 36.21,8.59 ; P11.3 84.9,6.1 ; P11.3 83.82,5.02 ; P11.3 83.82,7.18 ; 50.23,3.51 IN4.3 ; IN4.3 52.9,3.51 ; IN4.3 51.56,2.17 ; IN4.3 51.56,4.84 ; GND.1 65.89,12.23 ; GND.1 64.55,10.9 ; GND.1 65.89,9.56 ; GND.1 67.22,10.9 ; 87.38,47.12 88.27,47.12 88.27,47.88 ; 46.48,2.17 IN4.5 ; IN4.5 46.48,4.84 ; IN4.5 45.15,3.51 ; IN4.5 47.82,3.51 ; 51.49,49.77 IN1.4 ; IN1.4 50.15,51.1 ; IN1.4 51.49,52.44 ; IN1.4 52.82,51.1 ; IN1.2 47.74,51.1 ; IN1.2 46.41,52.44 ; IN1.2 45.07,51.1 ; IN1.2 46.41,49.77 ; IN3.5 34.87,4.84 ; IN3.5 36.21,3.51 ; IN3.5 33.54,3.51 ; IN3.5 34.87,2.17 ; 45.07,56.18 IN1.3 ; IN1.3 46.41,57.52 ; IN1.3 46.41,54.85 ; IN1.3 47.74,56.18 ; 33.54,51.1 IN2.2 ; IN2.2 34.87,49.77 ; IN2.2 34.87,52.44 ; IN2.2 36.21,51.1 ; C19.1 v1(51.34,19.4) ; C19.1 51.85,20.14 ; C19.1 50.83,20.14 ; v2(53.54,25.9) 53.58,25.95 53.58,26.48 R56.1 ; 39.95,54.85 IN2.5 ; IN2.5 39.95,57.52 ; IN2.5 38.62,56.18 ; IN2.5 41.29,56.18 ; 38.62,3.51 IN3.3 ; IN3.3 39.95,4.84 ; IN3.3 39.95,2.17 ; IN3.3 41.29,3.51 ; 46.02,15.96 D5.A 46.72,15.07 ; 96.39,47.88 96.39,47.12 95.5,47.12 ; IN1.5 51.49,57.52 ; IN1.5 51.49,54.85 ; IN1.5 52.82,56.18 ; IN1.5 50.15,56.18 ; 53.42,33.3 54.1,32.62 R55.2 ; 99.69,47.12 100.58,47.12 100.58,47.88 ; C29.1 v1(53.05,19.4) ; C29.1 52.54,20.14 ; C29.1 53.56,20.14 ; 86.36,8.88 GND1.1 ; GND1.1 87.69,10.21 ; GND1.1 85.03,10.21 ; GND1.1 86.36,11.54 ; 84.2,47.88 84.2,47.12 83.31,47.12 ; P11.2 86.36,7.18 ; P11.2 87.44,6.1 ; P11.2 86.36,5.02 ; P11.2 85.28,6.1 ; 4.62,34.75 P7.1 ; P7.1 5.89,33.48 ; P7.1 5.89,36.02 ; P7.1 7.16,34.75 ; C25.1 v1(54.26,19.38) ; IN4.2 51.56,9.92 ; IN4.2 52.9,8.59 ; IN4.2 51.56,7.25 ; IN4.2 50.23,8.59 ; R7.1 40.34,25.19 ; 46.48,7.25 IN4.4 ; IN4.4 46.48,9.92 ; IN4.4 45.15,8.59 ; IN4.4 47.82,8.59 ; 42.89,32.33 R6.1 42.89,34.28 ; C21.1 v1(50.13,19.38) ; 40.4,34.37 40.34,34.32 R2.1 ; C17.1 v1(44.9,25.86) ; DS1.C v1(73.27,8.61)
  L2_GND w0.508: P11.3 83.82,7.18 ; P11.3 83.82,5.02 ; P11.3 82.74,6.1 ; P11.3 84.9,6.1 ; 46.48,7.25 IN4.4 ; IN4.4 46.48,9.92 ; IN4.4 47.82,8.59 ; IN4.4 45.15,8.59 ; IN4.3 51.56,4.84 ; IN4.3 52.9,3.51 ; IN4.3 51.56,2.17 ; IN4.3 50.23,3.51 ; GND1.1 87.69,10.21 ; GND1.1 86.36,11.54 ; GND1.1 86.36,8.88 ; GND1.1 85.03,10.21 ; IN1.5 52.82,56.18 ; IN1.5 51.49,57.52 ; IN1.5 50.15,56.18 ; IN1.5 51.49,54.85 ; IN1.3 47.74,56.18 ; IN1.3 46.41,54.85 ; IN1.3 45.07,56.18 ; IN1.3 46.41,57.52 ; 46.41,49.77 IN1.2 ; IN1.2 46.41,52.44 ; IN1.2 45.07,51.1 ; IN1.2 47.74,51.1 ; IN1.4 52.82,51.1 ; IN1.4 51.49,52.44 ; IN1.4 51.49,49.77 ; IN1.4 50.15,51.1 ; P11.2 86.36,7.18 ; P11.2 87.44,6.1 ; P11.2 85.28,6.1 ; P11.2 86.36,5.02 ; 99.69,47.12 100.58,47.12 ; 100.58,47.12 100.58,47.88 ; 100.58,47.12 101.47,47.12 ; GND.1 67.22,10.9 ; GND.1 64.55,10.9 ; GND.1 65.89,9.56 ; GND.1 65.89,12.23 ; IN3.4 34.87,9.92 ; IN3.4 34.87,7.25 ; IN3.4 36.21,8.59 ; IN3.4 33.54,8.59 ; 104.65,47.12 105.54,47.12 ; 104.65,47.12 103.76,47.12 ; 104.65,47.12 104.65,47.88 ; 33.54,56.18 IN2.3 ; IN2.3 34.87,57.52 ; IN2.3 36.21,56.18 ; IN2.3 34.87,54.85 ; IN4.2 52.9,8.59 ; IN4.2 51.56,9.92 ; IN4.2 51.56,7.25 ; IN4.2 50.23,8.59 ; 39.95,7.25 IN3.2 ; IN3.2 39.95,9.92 ; IN3.2 38.62,8.59 ; IN3.2 41.29,8.59 ; 95.5,47.12 96.39,47.12 ; 96.39,47.12 97.28,47.12 ; 96.39,47.12 96.39,47.88 ; 38.62,56.18 IN2.5 ; IN2.5 41.29,56.18 ; IN2.5 39.95,54.85 ; IN2.5 39.95,57.52 ; IN3.3 39.95,4.84 ; IN3.3 39.95,2.17 ; IN3.3 38.62,3.51 ; IN3.3 41.29,3.51 ; 46.48,2.17 IN4.5 ; IN4.5 46.48,4.84 ; IN4.5 47.82,3.51 ; IN4.5 45.15,3.51 ; 84.2,47.12 85.09,47.12 ; 84.2,47.12 84.2,47.88 ; 84.2,47.12 83.31,47.12 ; 5.89,33.48 P7.1 ; P7.1 5.89,36.02 ; P7.1 7.16,34.75 ; P7.1 4.62,34.75 ; 88.27,47.12 88.27,47.88 ; 88.27,47.12 87.38,47.12 ; 88.27,47.12 89.15,47.12 ; IN2.2 34.87,52.44 ; IN2.2 36.21,51.1 ; IN2.2 34.87,49.77 ; IN2.2 33.54,51.1 ; 39.95,49.77 IN2.4 ; IN2.4 39.95,52.44 ; IN2.4 38.62,51.1 ; IN2.4 41.29,51.1 ; 91.44,47.12 92.33,47.12 ; 92.33,47.12 92.33,47.88 ; 92.33,47.12 93.22,47.12 ; IN3.5 34.87,4.84 ; IN3.5 33.54,3.51 ; IN3.5 36.21,3.51 ; IN3.5 34.87,2.17
  L3_VCC w0.508: IN2.4 39.95,52.44 ; IN2.4 38.62,51.1 ; IN2.4 41.29,51.1 ; 51.56,2.17 IN4.3 ; IN4.3 52.9,3.51 ; IN4.3 50.23,3.51 ; IN4.3 51.56,4.84 ; 46.48,2.17 IN4.5 ; IN4.5 47.82,3.51 ; IN4.5 45.15,3.51 ; IN4.5 46.48,4.84 ; 34.87,7.25 IN3.4 ; IN3.4 33.54,8.59 ; IN3.4 34.87,9.92 ; IN3.4 36.21,8.59 ; IN1.3 47.74,56.18 ; IN1.3 45.07,56.18 ; IN1.3 46.41,57.52 ; IN1.3 46.41,54.85 ; P7.1 7.16,34.75 ; P7.1 5.89,33.48 ; P7.1 4.62,34.75 ; P7.1 5.89,36.02 ; 46.48,7.25 IN4.4 ; IN4.4 46.48,9.92 ; IN4.4 47.82,8.59 ; IN4.4 45.15,8.59 ; 86.36,5.02 P11.2 ; P11.2 87.44,6.1 ; P11.2 85.28,6.1 ; P11.2 86.36,7.18 ; IN1.2 46.41,52.44 ; IN1.2 47.74,51.1 ; IN1.2 45.07,51.1 ; 65.89,9.56 GND.1 ; GND.1 67.22,10.9 ; GND.1 65.89,12.23 ; IN2.3 36.21,56.18 ; IN2.3 33.54,56.18 ; IN2.3 34.87,54.85 ; IN2.3 34.87,57.52 ; 51.49,54.85 IN1.5 ; IN1.5 51.49,57.52 ; IN1.5 50.15,56.18 ; IN1.5 52.82,56.18 ; 50.23,8.59 IN4.2 ; IN4.2 51.56,7.25 ; IN4.2 52.9,8.59 ; IN4.2 51.56,9.92 ; 36.21,51.1 IN2.2 34.87,52.44 ; 34.87,2.17 IN3.5 ; IN3.5 36.21,3.51 ; IN3.5 33.54,3.51 ; IN3.5 34.87,4.84 ; 83.82,5.02 P11.3 ; P11.3 83.82,7.18 ; P11.3 84.9,6.1 ; P11.3 82.74,6.1 ; IN1.4 52.82,51.1 ; IN1.4 51.49,52.44 ; IN1.4 50.15,51.1 ; 38.62,8.59 IN3.2 ; IN3.2 41.29,8.59 ; IN3.2 39.95,7.25 ; IN3.2 39.95,9.92 ; GND1.1 86.36,11.54 ; GND1.1 85.03,10.21 ; GND1.1 87.69,10.21 ; GND1.1 86.36,8.88 ; IN2.5 39.95,57.52 ; IN2.5 38.62,56.18 ; IN2.5 41.29,56.18 ; IN2.5 39.95,54.85 ; IN3.3 39.95,4.84 ; IN3.3 41.29,3.51 ; IN3.3 39.95,2.17 ; IN3.3 38.62,3.51
  L4_SIGNAL w0.508: IN2.3 34.87,57.52 ; IN2.3 36.21,56.18 ; IN2.3 34.87,54.85 ; IN2.3 33.54,56.18 ; 51.49,49.77 IN1.4 ; IN1.4 52.82,51.1 ; IN1.4 50.15,51.1 ; IN1.4 51.49,52.44 ; 82.74,6.1 P11.3 ; P11.3 84.9,6.1 ; P11.3 83.82,7.18 ; P11.3 83.82,5.02 ; 104.65,47.12 104.65,47.88 ; 104.65,47.12 103.76,47.12 ; 104.65,47.12 105.54,47.12 ; 38.62,56.18 IN2.5 ; IN2.5 41.29,56.18 ; IN2.5 39.95,54.85 ; IN2.5 39.95,57.52 ; 96.39,47.12 96.39,47.88 ; 96.39,47.12 97.28,47.12 ; 96.39,47.12 95.5,47.12 ; IN3.2 41.29,8.59 ; IN3.2 38.62,8.59 ; IN3.2 39.95,7.25 ; IN3.2 39.95,9.92 ; GND1.1 87.69,10.21 ; GND1.1 86.36,11.54 ; GND1.1 85.03,10.21 ; GND1.1 86.36,8.88 ; 64.55,10.9 GND.1 ; GND.1 67.22,10.9 ; GND.1 65.89,9.56 ; GND.1 65.89,12.23 ; IN3.5 34.87,4.84 ; IN3.5 36.21,3.51 ; IN3.5 34.87,2.17 ; IN3.5 33.54,3.51 ; 50.15,56.18 IN1.5 ; IN1.5 51.49,54.85 ; IN1.5 52.82,56.18 ; IN1.5 51.49,57.52 ; 45.15,8.59 IN4.4 ; IN4.4 46.48,9.92 ; IN4.4 46.48,7.25 ; IN4.4 47.82,8.59 ; 91.44,47.12 92.33,47.12 ; 92.33,47.12 93.22,47.12 ; 92.33,47.12 92.33,47.88 ; IN2.2 34.87,52.44 ; IN2.2 36.21,51.1 ; IN2.2 34.87,49.77 ; IN2.2 33.54,51.1 ; P11.2 87.44,6.1 ; P11.2 86.36,7.18 ; P11.2 86.36,5.02 ; P11.2 85.28,6.1 ; 87.38,47.12 88.27,47.12 ; 88.27,47.12 88.27,47.88 ; 88.27,47.12 89.15,47.12 ; 34.87,7.25 IN3.4 ; IN3.4 36.21,8.59 ; IN3.4 34.87,9.92 ; IN3.4 33.54,8.59 ; 84.2,47.12 85.09,47.12 ; 84.2,47.12 84.2,47.88 ; 84.2,47.12 83.31,47.12 ; IN2.4 41.29,51.1 ; IN2.4 39.95,52.44 ; IN2.4 39.95,49.77 ; IN2.4 38.62,51.1 ; 38.62,3.51 IN3.3 ; IN3.3 39.95,4.84 ; IN3.3 41.29,3.51 ; IN3.3 39.95,2.17 ; P7.1 7.16,34.75 ; P7.1 5.89,36.02 ; P7.1 4.62,34.75 ; P7.1 5.89,33.48 ; IN4.5 46.48,4.84 ; IN4.5 47.82,3.51 ; IN4.5 46.48,2.17 ; IN4.5 45.15,3.51 ; 45.07,56.18 IN1.3 ; IN1.3 46.41,54.85 ; IN1.3 47.74,56.18 ; IN1.3 46.41,57.52 ; IN1.2 46.41,52.44 ; IN1.2 45.07,51.1 ; IN1.2 47.74,51.1 ; IN1.2 46.41,49.77 ; 50.23,3.51 IN4.3 ; IN4.3 51.56,2.17 ; IN4.3 52.9,3.51 ; IN4.3 51.56,4.84 ; 100.58,47.12 101.47,47.12 ; 100.58,47.12 99.69,47.12 ; 100.58,47.12 100.58,47.88 ; 50.23,8.59 IN4.2 ; IN4.2 51.56,7.25 ; IN4.2 52.9,8.59 ; IN4.2 51.56,9.92
  L5_GND w0.508: 34.87,7.25 IN3.4 ; IN3.4 34.87,9.92 ; IN3.4 36.21,8.59 ; IN3.4 33.54,8.59 ; IN1.3 46.41,57.52 ; IN1.3 45.07,56.18 ; IN1.3 46.41,54.85 ; IN1.3 47.74,56.18 ; P11.2 87.44,6.1 ; P11.2 86.36,5.02 ; P11.2 86.36,7.18 ; P11.2 85.28,6.1 ; 92.33,47.12 93.22,47.12 ; 92.33,47.12 91.44,47.12 ; 92.33,47.12 92.33,47.88 ; 87.38,47.12 88.27,47.12 ; 88.27,47.12 89.15,47.12 ; 88.27,47.12 88.27,47.88 ; 33.54,56.18 IN2.3 ; IN2.3 34.87,54.85 ; IN2.3 34.87,57.52 ; IN2.3 36.21,56.18 ; P11.3 84.9,6.1 ; P11.3 82.74,6.1 ; P11.3 83.82,7.18 ; P11.3 83.82,5.02 ; 85.03,10.21 GND1.1 ; GND1.1 86.36,8.88 ; GND1.1 87.69,10.21 ; GND1.1 86.36,11.54 ; P7.1 7.16,34.75 ; P7.1 5.89,36.02 ; P7.1 4.62,34.75 ; P7.1 5.89,33.48 ; IN2.2 34.87,52.44 ; IN2.2 36.21,51.1 ; IN2.2 34.87,49.77 ; IN2.2 33.54,51.1 ; 103.76,47.12 104.65,47.12 ; 104.65,47.12 105.54,47.12 ; 104.65,47.12 104.65,47.88 ; 38.62,8.59 IN3.2 ; IN3.2 39.95,9.92 ; IN3.2 39.95,7.25 ; IN3.2 41.29,8.59 ; 99.69,47.12 100.58,47.12 ; 100.58,47.12 100.58,47.88 ; 100.58,47.12 101.47,47.12 ; 33.54,3.51 IN3.5 ; IN3.5 36.21,3.51 ; IN3.5 34.87,2.17 ; IN3.5 34.87,4.84 ; IN4.4 46.48,9.92 ; IN4.4 46.48,7.25 ; IN4.4 45.15,8.59 ; IN4.4 47.82,8.59 ; IN4.3 52.9,3.51 ; IN4.3 50.23,3.51 ; IN4.3 51.56,4.84 ; IN4.3 51.56,2.17 ; 46.41,49.77 IN1.2 ; IN1.2 45.07,51.1 ; IN1.2 47.74,51.1 ; IN1.2 46.41,52.44 ; 83.31,47.12 84.2,47.12 ; 84.2,47.12 84.2,47.88 ; 84.2,47.12 85.09,47.12 ; IN1.5 52.82,56.18 ; IN1.5 51.49,54.85 ; IN1.5 51.49,57.52 ; IN1.5 50.15,56.18 ; IN4.2 52.9,8.59 ; IN4.2 50.23,8.59 ; IN4.2 51.56,9.92 ; IN4.2 51.56,7.25 ; IN2.5 39.95,57.52 ; IN2.5 38.62,56.18 ; IN2.5 41.29,56.18 ; IN2.5 39.95,54.85 ; IN2.4 39.95,52.44 ; IN2.4 39.95,49.77 ; IN2.4 41.29,51.1 ; IN2.4 38.62,51.1 ; IN3.3 39.95,4.84 ; IN3.3 41.29,3.51 ; IN3.3 38.62,3.51 ; IN3.3 39.95,2.17 ; GND.1 67.22,10.9 ; GND.1 65.89,9.56 ; GND.1 65.89,12.23 ; GND.1 64.55,10.9 ; 50.15,51.1 IN1.4 ; IN1.4 51.49,49.77 ; IN1.4 52.82,51.1 ; IN1.4 51.49,52.44 ; 96.39,47.12 96.39,47.88 ; 96.39,47.12 95.5,47.12 ; 96.39,47.12 97.28,47.12 ; IN4.5 46.48,4.84 ; IN4.5 47.82,3.51 ; IN4.5 46.48,2.17 ; IN4.5 45.15,3.51
  BOTTOM w0.152: v1(42.48,31.2) 42.57,31.29 ; 42.57,28.32 v1(42.48,28.41)
  BOTTOM w0.457: R59.1 64,46.99 v1(64.52,46.48) ; R28.2 v1(82.04,43.58) ; 42.58,26.35 42.27,26.03 ; C5.2 v1(58.94,44.18)
  BOTTOM w0.508: 54.98,46.66 U5.2 ; U5.2 54.98,47.78 ; U5.2 56.33,47.22 ; U5.2 v1(53.3,47.22) ; IN1.4 51.49,52.44 ; IN1.4 52.82,51.1 ; IN1.4 50.15,51.1 ; IN1.4 51.49,49.77 ; U5.1 v1(53.3,45.95) ; U5.1 56.33,45.95 ; U5.1 54.98,46.51 ; U5.1 54.98,45.39 ; 5.89,33.48 P7.1 ; P7.1 4.62,34.75 ; P7.1 7.16,34.75 ; P7.1 5.89,36.02 ; 95.5,47.88 96.39,47.12 97.28,47.88 ; 44.83,26.03 R4.1 44.83,24.26 ; 93.22,47.88 92.33,47.12 91.44,47.88 ; 34.87,7.25 IN3.4 ; IN3.4 33.54,8.59 ; IN3.4 34.87,9.92 ; IN3.4 36.21,8.59 ; 45.77,35.06 C1.1 45.19,34.51 ; R16.1 v1(78.17,43.59) ; 65.99,44.34 R14.1 ; R14.1 v1(66.61,43.59) ; R14.1 67.23,44.34 ; 54.98,47.93 U5.3 ; U5.3 56.33,48.49 ; U5.3 54.98,49.05 ; U5.3 v1(53.3,48.49) ; 33.54,3.51 IN3.5 ; IN3.5 34.87,4.84 ; IN3.5 36.21,3.51 ; IN3.5 34.87,2.17 ; 46.41,49.77 IN1.2 ; IN1.2 46.41,52.44 ; IN1.2 47.74,51.1 ; IN1.2 45.07,51.1 ; 105.54,47.88 104.65,47.12 103.76,47.88 ; P11.2 86.36,7.18 ; P11.2 85.28,6.1 ; P11.2 86.36,5.02 ; 93.65,44.33 R21.1 ; R21.1 94.82,44.33 ; R21.1 v1(94.23,43.58) ; 39.95,49.77 IN2.4 ; IN2.4 41.29,51.1 ; IN2.4 39.95,52.44 ; IN2.4 38.62,51.1 ; IN3.2 39.95,9.92 ; IN3.2 39.95,7.25 ; IN3.2 41.29,8.59 ; IN3.2 38.62,8.59 ; 47.37,34.51 C3.1 46.79,35.06 ; R27.2 86.73,44.33 ; R27.2 v1(86.11,43.58) ; R27.2 85.48,44.33 ; 97.84,44.31 R24.1 ; R24.1 v1(98.42,43.58) ; R24.1 99.01,44.31 ; v1(44.83,34.92) R5.1 44.83,33.5 v1(44.73,33.4) ; IN2.5 39.95,57.52 ; IN2.5 41.29,56.18 ; IN2.5 39.95,54.85 ; IN2.5 38.62,56.18 ; IN3.3 41.29,3.51 ; IN3.3 39.95,2.17 ; IN3.3 38.62,3.51 ; IN3.3 39.95,4.84 ; 34.87,54.85 IN2.3 ; IN2.3 36.21,56.18 ; IN2.3 33.54,56.18 ; IN2.3 34.87,57.52 ; IN4.3 51.56,4.84 ; IN4.3 50.23,3.51 ; IN4.3 52.9,3.51 ; IN4.3 51.56,2.17 ; IN1.5 52.82,56.18 ; IN1.5 50.15,56.18 ; IN1.5 51.49,54.85 ; IN1.5 51.49,57.52 ; P11.3 83.82,7.18 ; P11.3 83.82,5.02 ; P11.3 82.74,6.1 ; P11.3 84.9,6.1 ; 82.66,44.33 R28.2 81.42,44.33 ; 83.31,47.88 84.2,47.12 85.09,47.88 ; R22.1 v1(90.17,43.58) ; R22.1 89.59,44.33 ; R22.1 90.75,44.33 ; 46.41,54.85 IN1.3 ; IN1.3 45.07,56.18 ; IN1.3 46.41,57.52 ; IN1.3 47.74,56.18 ; 34.87,49.77 IN2.2 ; IN2.2 36.21,51.1 ; IN2.2 34.87,52.44 ; IN2.2 33.54,51.1 ; U5.4 v1(53.3,49.76) ; U5.4 56.33,49.76 ; U5.4 54.98,49.2 ; U5.4 54.98,50.32 ; 101.9,44.31 R23.1 ; R23.1 v1(102.49,43.58) ; R23.1 103.07,44.31 ; 59.64,44.69 C5.2 59.64,43.67 ; 46.48,7.25 IN4.4 ; IN4.4 47.82,8.59 ; IN4.4 45.15,8.59 ; IN4.4 46.48,9.92 ; 101.47,47.88 100.58,47.12 99.69,47.88 ; 42.27,33.67 R1.1 42.27,35.41 ; 73.74,44.34 R15.1 ; R15.1 v1(74.36,43.54) ; R15.1 74.98,44.34 ; 45.15,3.51 IN4.5 ; IN4.5 47.82,3.51 ; IN4.5 46.48,2.17 ; IN4.5 46.48,4.84 ; 42.27,24.28 R8.1 42.27,26.03 ; IN4.2 52.9,8.59 ; IN4.2 50.23,8.59 ; IN4.2 51.56,7.25 ; IN4.2 51.56,9.92 ; 69.93,44.34 R13.1 ; R13.1 v1(70.55,43.59) ; R13.1 71.17,44.34 ; 89.15,47.88 88.27,47.12 87.38,47.88
  vias: v1(2.68,22.99) v1(2.68,20.45) v1(2.68,17.91) v1(2.68,15.37) v1(2.68,12.83) v1(2.68,10.29) v1(2.68,7.75) v1(5.22,22.99) v1(5.22,20.45) v1(5.22,17.91) v1(5.22,15.37) v1(5.22,12.83) v1(5.22,10.29) v1(5.22,7.75) v1(7.76,22.99) v1(7.76,20.45) v1(7.76,17.91) v1(7.76,15.37) v1(7.76,12.83) v1(7.76,10.29) v1(7.76,7.75) v1(7.93,5.25) v1(7.93,2.71) v1(8.91,56.22) v1(8.91,53.68) v1(8.91,51.14) v1(8.91,47.69) v1(8.91,45.15) v1(8.91,42.61) v1(8.91,40.07) v1(8.91,37.53) v1(10.3,22.99) v1(10.3,20.45) v1(10.3,17.91) v1(10.3,15.37) v1(10.3,12.83) v1(10.3,10.29) v1(10.3,7.75) v1(10.47,5.25) v1(10.47,2.71) v1(11.45,56.22) v1(11.45,53.68) v1(11.45,51.14) v1(11.45,47.69) v1(11.45,45.15) v1(11.45,42.61) v1(11.45,40.07) v1(11.45,37.53) v1(12.84,22.99) v1(12.84,20.45) v1(12.84,17.91) v1(12.84,15.37) v1(12.84,12.83) v1(12.84,10.29) v1(12.84,7.75) v1(13.01,5.25) v1(13.01,2.71) v1(13.99,56.22) v1(13.99,53.68) v1(13.99,51.14) v1(13.99,47.69) v1(13.99,45.15) v1(13.99,42.61) v1(13.99,40.07) v1(13.99,37.53) v1(15.38,22.99) v1(15.38,20.45) v1(15.38,17.91) v1(15.38,15.37) v1(15.38,12.83) v1(15.38,10.29) v1(15.38,7.75) v1(15.55,5.25) v1(15.55,2.71) v1(16.53,56.22) v1(16.53,53.68) v1(16.53,51.14) v1(16.53,47.69) v1(16.53,45.15) v1(16.53,42.61) v1(16.53,40.07) v1(16.53,37.53) v1(17.92,22.99) v1(17.92,20.45) v1(17.92,17.91) v1(17.92,15.37) v1(17.92,12.83) v1(17.92,10.29) v1(17.92,7.75) v1(17.97,5.25) v1(17.97,2.71) v1(19.07,56.22) v1(19.07,53.68) v1(19.07,51.14) v1(20.26,10.4) v1(20.26,7.86) v1(20.26,5.32) v1(20.26,2.78) v1(21.61,56.22) v1(21.61,53.68) v1(21.61,51.14) v1(22.8,10.4) v1(22.8,7.86) v1(22.8,5.32) v1(22.8,2.78) v1(24.15,56.22) v1(24.15,53.68) v1(24.15,51.14) v1(25.34,10.4) v1(25.34,7.86) v1(25.34,5.32) v1(25.34,2.78) v1(26.69,56.22) v1(26.69,53.68) v1(26.69,51.14) v1(27.88,10.4) v1(27.88,7.86) v1(27.88,5.32) v1(27.88,2.78) v1(29.23,56.22) v1(29.23,53.68) v1(29.23,51.14) v1(30.42,10.4) v1(30.42,7.86) v1(30.42,5.32) v1(30.42,2.78) v1(31.77,56.22) v1(31.77,53.68) v1(31.77,51.14) v1(42.67,27.79) v1(43.31,29.82) v1(44.01,29.82) v1(44.83,30.4) v1(44.83,29.84) v1(44.83,29.21) v1(45.47,16) v1(45.53,30.39) v1(45.53,29.82) v1(45.53,29.25) v1(45.97,14.61) v1(46.36,29.82) v1(46.61,14.61) v1(47.5,24.81) v1(47.88,33.91) v1(48.64,24.77) v1(52.43,16.4) v1(52.43,15.82) v1(52.43,15.19) v1(52.43,14.62) v1(52.43,13.98) v1(52.62,18.55) v1(52.62,17.92) v1(53,16.4) v1(53,15.82) v1(53,14.62) v1(53,13.98) v1(53.02,15.19) v1(53.38,18.55) v1(53.38,17.92) v1(53.63,16.4) v1(53.63,15.82) v1(53.63,15.19) v1(53.63,14.62) v1(53.63,13.98) v1(60.35,17.99) v1(60.35,15.45) v1(61.67,51.44) v1(61.67,50.16) v1(62.31,50.8) v1(62.81,51.44) v1(62.81,50.16) v1(62.89,17.99) v1(62.89,15.45) v1(65.43,17.99) v1(65.43,15.45) v1(67.97,17.99) v1(67.97,15.45) v1(70.51,17.99) v1(70.51,15.45) v1(73.05,17.99) v1(73.05,15.45) v1(75.59,17.99) v1(75.59,15.45) v1(78.13,17.99) v1(78.13,15.45) v1(80.67,17.99) v1(80.67,15.45) v1(83.21,17.99) v1(83.21,15.45) v1(85.75,17.99) v1(85.75,15.45) v1(88.29,17.99) v1(88.29,15.45) v1(90.83,17.99) v1(90.83,15.45) v1(93.37,17.99) v1(93.37,15.45) v1(93.48,12.62) v1(93.48,10.08) v1(95.91,17.99) v1(95.91,15.45) v1(96.02,12.62) v1(96.02,10.08) v1(98.45,17.99) v1(98.45,15.45) v1(98.56,12.62) v1(98.56,10.08) v1(100.99,17.99) v1(100.99,15.45) v1(101.1,12.62) v1(101.1,10.08) v1(103.53,17.99) v1(103.53,15.45) v1(103.64,12.62) v1(103.64,10.08) v1(106.18,12.62) v1(106.18,10.08) v2(27.05,28.7) v2(28.96,28.7) v2(30.99,28.7) v2(33.02,28.7) v2(34.92,28.7) v2(36.21,50.01) v2(36.2,9.55) v2(36.38,10.81) v2(36.41,48.76) v2(36.58,28.7) v2(36.69,12.04) v2(37.14,13.23) v2(37.46,31.62) v2(37.46,30.23) v2(37.46,28.83) v2(37.59,27.81) v2(37.77,45.21) v2(37.7,14.37) v2(38.39,15.44) v2(38.46,44.15) v2(38.67,50.01) v2(38.65,9.55) v2(38.88,10.8) v2(38.91,48.76) v2(39.19,16.42) v2(39.28,43.18) v2(39.24,31.62) v2(39.24,30.23) v2(39.24,28.83) v2(39.27,12.01) v2(39.5,27.81) v2(39.82,13.16) v2(39.96,42.11) v2(39.91,17.47) v2(40.34,40.89) v2(40.4,39.62) v2(40.4,38.35) v2(40.4,37.08) v2(40.4,35.81) v2(40.4,34.54) v2(40.4,25.2) v2(40.4,23.75) v2(40.4,22.48) v2(40.4,21.21) v2(40.4,19.94) v2(40.31,18.67) v2(40.6,45.37) v2(40.52,14.22) v2(41.34,15.19) v2(41.42,44.4) v2(42.08,43.32) v2(42.03,16.26) v2(42.55,42.14) v2(42.51,17.43) v2(42.8,40.89) v2(42.8,38.86) v2(42.78,18.67) v2(42.84,19.94) v2(43.35,39.79) v2(43.82,19.25) v2(44.2,40.74) v2(45.1,41.64) v2(45.01,37.82) v2(45.49,38.57) v2(45.99,42.54) v2(46.38,39.47) v2(46.74,43.57) v2(47.3,44.71) v2(47.28,40.37) v2(47.65,45.93) v2(47.78,49.99) v2(47.78,48.72) v2(48.13,41.31) v2(48.86,42.36) v2(49.43,43.49) v2(49.86,44.68) v2(49.85,27.91) v2(50.12,45.93) v2(50.22,49.99) v2(50.22,48.72) v2(50.67,31.53) v2(50.99,27.91) v2(51.63,31.72) v2(51.94,27.66) v2(52.39,32.3) v2(53.15,27.34) v2(53.28,32.3) v2(53.61,33.65) v2(54.35,26.17) v2(54.77,33.74) v2(55.06,25.45) v2(55.65,34.66) v2(55.6,31.12) v2(55.96,24.56) v2(56.33,27.63) v2(56.5,32.02) v2(56.57,35.53) v2(56.91,23.72) v2(57.23,26.74) v2(57.4,32.91) v2(57.56,36.36) v2(57.92,22.95) v2(58.15,25.86) v2(58.33,33.78) v2(58.6,37.09) v2(58.98,22.25) v2(59.14,25.07) v2(59.33,34.56) v2(59.69,37.76) v2(60.09,21.63) v2(60.2,24.36) v2(60.39,35.26) v2(60.83,38.33) v2(61.24,21.09) v2(61.31,23.75) v2(61.5,35.87) v2(61.97,38.82) v2(62.47,23.23) v2(62.43,20.64) v2(62.67,36.38) v2(63.18,39.22) v2(63.66,22.8) v2(63.65,20.27) v2(63.87,36.79) v2(64.36,39.55) v2(64.89,22.48) v2(64.88,19.99) v2(65.1,37.1) v2(65.61,39.78) v2(66.14,22.26) v2(66.14,19.81) v2(66.35,37.3) v2(66.97,39.94) v2(67.41,22.15) v2(67.41,19.71) v2(67.62,37.41) v2(68.24,39.98) v2(68.68,22.13) v2(68.68,19.69) v2(68.89,37.42) v2(69.51,39.98) v2(69.95,22.13) v2(69.95,19.69) v2(70.16,37.42) v2(70.78,39.98) v2(71.22,22.13) v2(71.22,19.69) v2(71.43,37.42) v2(72.05,39.98) v2(72.49,22.13) v2(72.49,19.69) v2(72.7,37.42) v2(73.32,39.98) v2(73.76,22.13) v2(73.76,19.69) v2(73.97,37.42) v2(74.59,39.98) v2(75.03,22.13) v2(75.03,19.69) v2(75.24,37.42) v2(75.86,39.98) v2(76.3,22.13) v2(76.3,19.69) v2(76.51,37.42) v2(77.13,39.98) v2(77.57,22.13) v2(77.57,19.69) v2(77.78,37.42) v2(78.4,39.98) v2(78.84,22.13) v2(78.84,19.69) v2(79.05,37.42) v2(79.67,39.98) v2(80.11,22.13) v2(80.11,19.69) v2(80.32,37.42) v2(80.94,39.98) v2(81.38,22.13) v2(81.38,19.69) v2(81.59,37.42) v2(82.21,39.98) v2(82.65,22.13) v2(82.65,19.69) v2(82.86,37.42) v2(83.48,39.98) v2(83.92,22.13) v2(83.92,19.69) v2(84.13,37.42) v2(84.75,39.98) v2(85.19,22.13) v2(85.19,19.69) v2(85.4,37.42) v2(86.02,39.98) v2(86.46,22.13) v2(86.46,19.69) v2(86.67,37.42) v2(87.29,39.98) v2(87.73,22.13) v2(87.73,19.69) v2(87.94,37.42) v2(88.56,39.98) v2(89,22.13) v2(89,19.69) v2(89.21,37.42) v2(89.83,39.98) v2(90.27,22.13) v2(90.27,19.69) v2(90.48,37.42) v2(91.1,39.98) v2(91.54,22.13) v2(91.54,19.69) v2(91.75,37.42) v2(92.37,39.98) v2(92.81,22.13) v2(92.81,19.69) v2(93.02,37.42) v2(93.64,39.98) v2(94.08,22.13) v2(94.08,19.69) v2(94.29,37.42) v2(94.91,39.98) v2(95.35,22.13) v2(95.35,19.69) v2(95.56,37.42) v2(96.18,39.98) v2(96.62,22.13) v2(96.62,19.69) v2(96.83,37.42) v2(97.45,39.98) v2(97.89,22.13) v2(97.89,19.69) v2(98.1,37.42) v2(98.72,39.98) v2(99.16,22.13) v2(99.16,19.69) v2(99.37,37.42) v2(99.99,39.98) v2(100.43,22.13) v2(100.43,19.69) v2(100.64,37.42) v2(101.26,39.98) v2(101.7,22.13) v2(101.7,19.69) v2(101.91,37.42) v2(102.53,39.98) v2(102.97,22.13) v2(102.97,19.69) v2(103.18,37.42) v2(103.8,39.98) v2(104.24,22.13) v2(104.24,19.69) v2(104.45,37.42) v2(105.07,39.98) v2(105.51,22.13) v2(105.51,19.69) v2(105.72,37.42) v2(105.94,22.89) v2(106.17,26.9) v2(106.17,18.14) v2(106.21,44.66) v2(106.21,43.65) v2(106.21,42.38) v2(106.29,41.49) v2(106.24,35.92) v2(106.27,34.88) v2(106.27,33.61) v2(106.27,32.6) v2(106.21,25.87) v2(106.21,24.6) v2(106.21,23.58) v2(106.21,17.1) v2(106.21,15.83) v2(106.21,14.82) v2(106.35,40.67) v2(106.34,39.98) v2(106.3,18.93) v2(106.78,22.13) v2(106.78,19.69) v2(106.99,37.42) v2(107.22,44.79) v2(107.22,41.36) v2(107.29,36.03) v2(107.29,32.6) v2(107.22,27.01) v2(107.22,23.58) v2(107.22,18.25) v2(107.22,14.82) v2(107.61,39.98) v2(108.05,22.13) v2(108.05,19.69) v2(108.24,44.79) v2(108.24,41.36) v2(108.26,37.42) v2(108.24,27.01) v2(108.24,23.58) v2(108.24,18.25) v2(108.24,14.82) v2(108.3,36.03) v2(108.3,32.6) v2(108.88,39.98) v2(109.25,44.79) v2(109.25,41.36) v2(109.25,27.01) v2(109.25,23.58) v2(109.25,18.25) v2(109.25,14.82) v2(109.35,37.34) v2(109.32,36.03) v2(109.32,32.6) v2(109.32,22.13) v2(109.32,19.69) v2(110.3,44.81) v2(110.27,41.36) v2(110.3,27.03) v2(110.27,23.58) v2(110.3,18.26) v2(110.36,37.34) v2(110.36,36.04) v2(110.33,32.6) v2(110.41,40.17)
VCCI: length 4.1
  TOP w0.508: VCCI.1 48.01,22.35 ; VCCI.1 46.99,21.34 ; VCCI.1 48.01,20.32 ; VCCI.1 49.02,21.34
  TOP w0.559: 45.85,23.11 45.85,23.11
VCCO: length 49
  TOP w0.305: v1(65.25,48.39) C26.2 64.39,48.47 U2.1
  TOP w0.457: U1.8 31.06,49.43
  TOP w0.508: R63.2 v1(56.52,11.05) ; v1(32.92,47.17) R43.2 ; v1(32.91,45.33) R44.2 ; VCCO.1 57.59,21.12 ; VCCO.1 55.56,21.12 ; VCCO.1 56.58,22.14 ; VCCO.1 56.58,20.1 ; R50.2 v1(46.47,37.77)
  L3_VCC w0.508: 96.39,43.81 SHDN.1 ; SHDN.1 95.5,44.58 ; SHDN.1 97.28,44.58 ; VCCO.1 56.58,22.14 ; VCCO.1 57.59,21.12 ; VCCO.1 55.56,21.12 ; VCCO.1 56.58,20.1 ; 83.31,44.58 CHSEL0.1 ; CHSEL0.1 85.09,44.58 ; CHSEL0.1 84.2,43.81 ; 103.76,44.58 ADJ0.1 104.65,43.81 ; 100.58,43.81 ADJ1.1 ; ADJ1.1 99.69,44.58 ; ADJ1.1 101.47,44.58 ; 88.27,43.81 CHSEL1.1 ; CHSEL1.1 89.15,44.58 ; CHSEL1.1 87.38,44.58 ; MUX.1 93.22,44.58 ; MUX.1 91.44,44.58 ; MUX.1 92.33,43.81
  BOTTOM w0.305: v1(57.12,17.92) 57.91,17.13 57.91,11.43 57.53,11.05 v1(56.52,11.05)
  BOTTOM w0.457: R71.2 71.13,53.48 v1(70.92,53.7) ; R58.2 v1(63.41,44.79) ; R57.2 65.05,48.18 v1(65.25,48.39) ; R68.2 v1(84.13,52.7) ; R70.2 v1(76.21,53.59) ; R69.2 v1(81.53,52.7) ; U5.8 60.06,45.35 60.6,44.81 C5.1 v1(61.58,44.18)
  BOTTOM w0.508: R60.2 63.41,48.19 R57.2
  vias: v1(32.79,49.56) v1(32.79,48.92) v1(55.85,18.55) v1(55.85,17.92) v1(56.49,18.55) v1(56.49,17.92) v1(57.12,18.55)
DAC_CM: length 14.9
  TOP w0.203: P1.3 67.64,49.44 65.34,47.14 59.54,47.14 58.83,47.85 58.83,50.22 59.43,50.82 U2.8
DAC_CS: length 18.3
  TOP w0.203: P8.3 77.19,51.79 66.08,51.79 65.61,51.32 U2.4
  BOTTOM w0.254: P8.3 79.76,52.71 R69.1
DAC_HI: length 16.7
  TOP w0.203: U2.3 65.76,50.82 66.27,51.33 78.18,51.33 P4.3
DAC_OFFSET: length 12.7
  TOP w0.203: U2.2 66.02,50.32 66.62,50.93 74.78,50.93 P3.3
DAC_TILT: length 18.6
  TOP w0.203: U2.9 59.51,50.32 59.23,50.05 59.23,48.06 59.74,47.55 65.17,47.55 67.21,49.59 67.21,50.37 67.36,50.52 71.37,50.52 P2.3
DC2026C_ADJ0: length 6.9
  TOP w0.254: P20.1 102.47,50.95 P9.4
DC2026C_ADJ1: length 6.1
  TOP w0.254: P21.1 100.43,50.93 98.63,50.93 96.52,53.04 P9.5
DC2026C_CHSEL0: length 3.7
  TOP w0.254: P8.1 84.84,51.71 P19.1
DC2026C_CHSEL1: length 3.7
  TOP w0.254: P13.1 88.9,51.71 P9.8
DC2026C_O_MUX: length 3.7
  TOP w0.254: P15.1 91.44,51.71 P9.7
DC2026C_SHDN: length 5.2
  TOP w0.254: P14.1 96.24,50.98 94.77,50.98 93.98,51.77 P9.6
DC2026C_VIN: length 3.2
  BOTTOM w0.508: P11.1 89.98,6.1 ; P11.1 88.9,7.18 ; P11.1 88.9,5.02
  vias: v1(62.51,8.5) v1(62.51,7.92) v1(63.21,8.5) v1(63.21,7.92) v1(63.97,8.5) v1(63.97,7.92) v1(64.67,8.5) v1(64.67,7.92)
EEPROM_SCL: length 12.5
  BOTTOM w0.203: R57.1 62.21,48.39 60.16,48.39 U5.6 58.7,48.49 58.7,48.51 58.12,49.1 58.12,52.14 60.33,54.36 P8.10
EEPROM_SDA: length 13.1
  BOTTOM w0.203: P8.9 63.27,53.11 59.66,53.11 58.52,51.97 58.52,50.01 58.77,49.76 U5.5 60.19,49.63 62.1,49.63 R60.1
IN1: length 15.5
  TOP w0.254: v1(43.56,32.08) 43.55,32.07 U4.19
  TOP w0.305: R39.2 v1(38.66,41.83)
  BOTTOM w0.305: v1(38.66,41.83) 39.34,41.14 39.34,33.05 39.72,32.67 R64.2
  BOTTOM w0.61: R64.2 43.56,32.67 v1(43.56,32.08)
IN2: length 5.9
  TOP w0.305: R40.2 38.64,33.78 41.23,31.19 41.63,31.19 R65.2 41.63,30.86 41.94,30.55 U4.21
IN3: length 5.9
  TOP w0.305: R41.2 38.56,25.74 41.23,28.42 R66.2 41.63,28.75 41.94,29.05 U4.24
IN4: length 15.6
  TOP w0.305: v1(43.56,27.53) 43.55,27.54 U4.2 ; R42.2 v1(38.66,17.7)
  BOTTOM w0.305: v1(38.66,17.7) 39.34,18.38 39.34,26.56 39.72,26.93 R67.2
  BOTTOM w0.61: R67.2 43.56,26.94 v1(43.56,27.53)
LTC6563_ADJ0: length 83.7
  TOP w0.254: v1(41.12,30.33) 41.12,30.31 41.38,30.05 U4.22
  L4_SIGNAL w0.203: v1(103.37,45.33) 98.83,40.79 88.44,40.79 87.9,40.25 87.9,39.6 87.28,38.98 87.28,37.16 78.92,28.8 49.58,28.8 49.21,28.43 49.21,24.58 48.48,23.85 44.15,23.85 40.49,27.52 40.49,29.69 v1(41.12,30.33)
  BOTTOM w0.254: R19.2 R23.2 103.32,45.31 arc(103.35,45.32) v1(103.37,45.33)
